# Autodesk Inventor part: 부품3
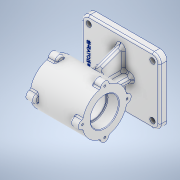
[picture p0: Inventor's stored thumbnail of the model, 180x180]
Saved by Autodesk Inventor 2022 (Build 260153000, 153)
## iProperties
Created: 2023-05
Part Number: 부품3
Material: 알루미늄 6061
Document SubType Name: Modeling
Designer: Admin
Density: 2.7 g/cm^3
Appearance: 알루미늄 - 평지
Mass: 1215.19 g
Surface Area: 797.778 cm^2
Volume: 450.069 cm^3
Author: Admin
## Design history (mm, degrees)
sketch "스케치1"
  geometry: L1 (-65, 55)-(65, 55); L2 (65, 55)-(65, -55); L3 (65, -55)-(-65, -55); L4 (-65, -55)-(-65, 55); L5 (-91, 0)-(91, 0) reference; L6 (0, -77)-(0, 77) reference; 1 further point
  constraints: 8 end point, 2 parallel, 1 horizontal, 1 perpendicular, 2 other
  dimensions: "d0" = 130 distance of L1.start L1.end; "d1" = 110 distance of L1.end L2.end
extrude "돌출1" new body sketch "스케치1" stored distance "d2" = 12; taper "d3" = 0 deg
sketch "스케치2"
  geometry: L1 (95.889, 76)-(-83.31, 76); L2 (-65, -6)-(65, -6) reference; L3 (-43.5, 76)-(43.5, 76); L4 (43.5, 76)-(43.5, 113); L5 (43.5, 113)-(-43.5, 113); L6 (-43.5, 113)-(-43.5, 76); L7 (0, -29.8)-(0, 136.8) reference; 2 further points
  constraints: 10 end point, 2 horizontal, 2 parallel, 1 perpendicular, 1 point on line, 1 other
  dimensions: "d4" = 82 distance between parallel lines of L2 L1; "d5" = 74 diameter of L5.end L1; "d6" = 87 distance of L4.end L5.end
revolve "회전1" sketch "스케치2" stored, may be unused: angle "d7" = 90 deg
sketch "스케치3"
  geometry: L1 (65, 6)-(-65, 6) reference; L2 (20, 6)-(20, 62.593); L3 (20, 62.593)-(-20, 62.593); L4 (-20, 62.593)-(-20, 6); L5 (20, 6)-(-20, 6); L6 (0, -29.8)-(0, 136.8) reference; 1 further point
  constraints: 8 end point, 3 perpendicular, 2 point on line, 1 collinear, 1 other
  dimensions: "d8" = 40 distance of L2.end L3.end; "d9" = 56.59267 distance of L3.end L4.end
extrude "돌출2" join sketch "스케치3" stored distance "d10" = 10; taper "d11" = 0 deg
sketch "스케치4"
  geometry: L1 (55, 6)-(-55, 6) reference; L2 (-41, 6)-(-14.452, 78.94); L3 (-55, 6)-(-55, -6) reference; 1 further point
  constraints: 2 end point, 1 point on line
  dimensions: "d12" = 110 deg angle of L1 L2; "d13" = 14 distance from line of L3 L2.start
feature "리브1" sketch "스케치4" dims "d14" = 1, "d15" = 10, "d16" = 0, "d17" = 0, "d18" = 1, "d19" = 1
sketch "스케치5"
  geometry: L1 (102.925, 76)-(-132.789, 76); L2 (65, -6)-(-65, -6) reference; L3 (-43.5, 39)-(-43.5, 113) reference; L4 (-43.5, 76)-(-24.5, 76); L5 (-24.5, 76)-(-24.5, 99.5); L6 (-24.5, 99.5)-(-43.5, 99.5); L7 (-43.5, 99.5)-(-43.5, 76); L8 (-24.5, 76)-(24.5, 76); L9 (24.5, 76)-(24.5, 97); L10 (24.5, 97)-(-24.5, 97); L11 (-24.5, 97)-(-24.5, 76); L12 (43.5, 39)-(43.5, 113) reference; L13 (24.5, 76)-(43.5, 76); L14 (43.5, 76)-(43.5, 99.5); L15 (43.5, 99.5)-(24.5, 99.5); L16 (24.5, 99.5)-(24.5, 76); L17 (0, -29.8)-(0, 136.8) reference; 5 further points
  constraints: 26 end point, 6 parallel, 4 horizontal, 3 perpendicular, 1 midpoint, 1 point on line
  dimensions: "d20" = 82 distance between parallel lines of L2 L1; "d21" = 47 diameter of L6.end L1; "d22" = 47 diameter of L14.end L1; "d23" = 42 diameter of L9.end L1; "d24" = 19 distance of L5.end L6.end; "d25" = 19 distance of L14.end L15.end
revolve "회전2" sketch "스케치5" stored, may be unused: angle "d26" = 90 deg
sketch "스케치6"
  geometry: L1 (107.2, 0)-(-69.2, 0) reference; C1 r 23.5 at (0, 0) reference; C2 r 7 at (-37, 0); 2 further points
  constraints: 1 centre point, 1 horizontal alignment, 1 point on line, 1 other
  dimensions: "d56" = 14 diameter of C2
extrude "돌출3" join sketch "스케치6" distance "d28" = 14; taper "d29" = 0 deg
fillet "모깎기1" dims "d43" = 12
sketch "스케치8"
  geometry: C1 r 4.5 at (-53, 43); A1 r 12 centre (-53, 43) between (-53, 55) and (-65, 43) reference; 1 further point
  constraints: 1 centre point, 1 coincident
  dimensions: "d44" = 9 diameter of C1
extrude "돌출4" cut sketch "스케치8" distance "d45" = 14; taper "d46" = 0 deg
fillet "모깎기2" dims "d47" = 1
chamfer "모따기1" distance "d48" = 1; stored, may be unused: second distance "d49" = 2, angle "d50" = 45 deg
fillet "모깎기3" dims "d51" = 3
fillet "모깎기4" dims "d52" = 3
fillet "모깎기6" dims "d57" = 3
sketch "스케치9"
  geometry: C1 r 4.5 at (-53, -43) reference; 2 further points
  constraints: 1 horizontal alignment, 1 vertical alignment, 1 other
feature "엠보싱1" sketch "스케치9" dims "d0" = 130, "d1" = 110, "d54" = 0.5, "d55" = 0
sketch "스케치11"
  geometry: A1 r 7 centre (-74, 0) between (-75.239, 6.889) and (-75.239, -6.889) reference; 2 further points
  constraints: 1 coincident
hole "구멍3" sketch "스케치11" at (-74, 0) diameter "d68" = 3.242; stored, may be unused: countersink angle "d72" = 90 deg, drill point angle "d74" = 118 deg; dims "d69" = 8, "d70" = 4, "d71" = 2, "d73" = 10
node "솔리드1"
mirror "미러1"
pattern_circular "원형 패턴1" dims angle "d31" = 360 deg
mirror "미러2"
mirror "미러4"
mirror "미러5"
pattern_circular "원형 패턴4" dims angle "d76" = 360 deg
mirror "미러7"
node "투영된 루프1"
feature "A9D066F2-1C7D-4E18-AEED-F7BC21143FA4" dims "d68" = 3.242, "d69" = 8, "d70" = 4, "d71" = 2, "d72" = 90 deg, "d73" = 10, "d74" = 118 deg
